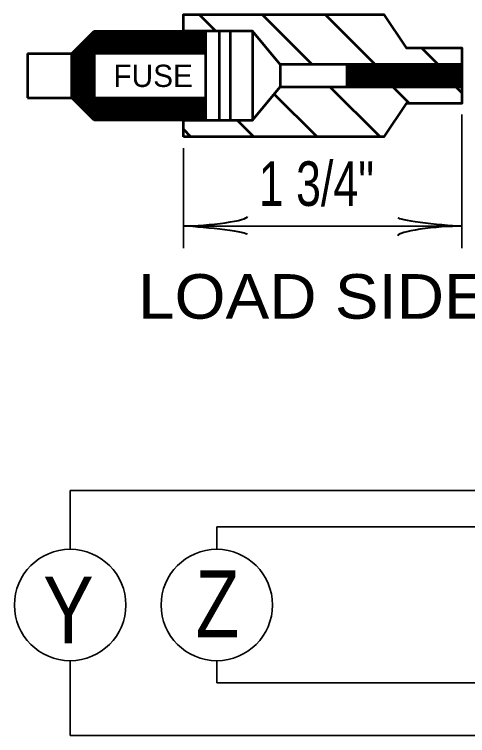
# Model space of a CAD drawing. Extents: x -1 to 679, y 0 to 440.
# Drawn here: x 328.32 to 348.66, y 299.14 to 331.51 of the extents above; entities that cross this region are included whole.
import ezdxf

# ---------------------------------------------------------------- set-up
doc = ezdxf.new("R2010")
doc.units = 0
doc.header["$LTSCALE"] = 0.8
doc.layers.add('1', color=7, linetype='Continuous', lineweight=53)

msp = doc.modelspace()

# ---------------------------------------------------------------- linework, layer by layer
at = {"layer": '1'}
for p, q in [((337.3586, 330.7649), (336.6086, 331.5149)), ((341.687, 329.2649), (339.437, 331.5149)), ((344.5154, 329.2649), (342.2654, 331.5149)), ((330.9045, 329.7649), (331.9045, 330.7649)), ((330.9045, 329.7389), (331.9305, 330.7649)), ((330.9045, 329.5975), (332.0719, 330.7649)), ((330.9045, 329.4561), (332.2133, 330.7649)), ((330.9045, 329.3147), (332.3547, 330.7649)), ((330.9045, 329.1732), (332.4962, 330.7649)), ((330.9045, 329.0318), (332.6376, 330.7649)), ((330.9045, 328.8904), (332.779, 330.7649)), ((332.4819, 329.7649), (331.6932, 330.5536)), ((332.6233, 329.7649), (331.7639, 330.6243)), ((332.7647, 329.7649), (331.8346, 330.695)), ((331.9045, 330.7649), (335.9045, 330.7649)), ((332.9062, 329.7649), (331.9062, 330.7649)), ((331.9204, 329.7649), (332.9204, 330.7649)), ((333.0476, 329.7649), (332.0476, 330.7649)), ((332.0618, 329.7649), (333.0618, 330.7649)), ((333.189, 329.7649), (332.189, 330.7649)), ((332.2032, 329.7649), (333.2032, 330.7649)), ((333.3304, 329.7649), (332.3304, 330.7649)), ((332.3447, 329.7649), (333.3447, 330.7649)), ((333.4718, 329.7649), (332.4718, 330.7649)), ((332.4861, 329.7649), (333.4861, 330.7649)), ((333.6132, 329.7649), (332.6132, 330.7649)), ((332.6275, 329.7649), (333.6275, 330.7649)), ((333.7547, 329.7649), (332.7547, 330.7649)), ((332.7689, 329.7649), (333.7689, 330.7649)), ((333.8961, 329.7649), (332.8961, 330.7649)), ((332.9104, 329.7649), (333.9104, 330.7649)), ((334.0375, 329.7649), (333.0375, 330.7649)), ((333.0518, 329.7649), (334.0518, 330.7649)), ((334.1789, 329.7649), (333.1789, 330.7649)), ((333.1932, 329.7649), (334.1932, 330.7649)), ((334.3204, 329.7649), (333.3204, 330.7649)), ((333.3347, 329.7649), (334.3347, 330.7649)), ((334.4618, 329.7649), (333.4618, 330.7649)), ((333.4761, 329.7649), (334.4761, 330.7649)), ((334.6033, 329.7649), (333.6033, 330.7649)), ((333.6175, 329.7649), (334.6175, 330.7649)), ((334.7447, 329.7649), (333.7447, 330.7649)), ((333.7589, 329.7649), (334.7589, 330.7649)), ((334.8861, 329.7649), (333.8861, 330.7649)), ((333.9003, 329.7649), (334.9003, 330.7649)), ((335.0275, 329.7649), (334.0275, 330.7649)), ((334.0417, 329.7649), (335.0417, 330.7649)), ((335.1689, 329.7649), (334.1689, 330.7649)), ((334.1832, 329.7649), (335.1832, 330.7649)), ((335.3103, 329.7649), (334.3103, 330.7649)), ((334.3246, 329.7649), (335.3246, 330.7649)), ((335.4518, 329.7649), (334.4518, 330.7649)), ((334.466, 329.7649), (335.466, 330.7649)), ((335.5932, 329.7649), (334.5932, 330.7649)), ((334.6074, 329.7649), (335.6074, 330.7649)), ((335.7346, 329.7649), (334.7346, 330.7649)), ((334.7488, 329.7649), (335.7488, 330.7649)), ((335.876, 329.7649), (334.876, 330.7649)), ((334.8902, 329.7649), (335.8902, 330.7649)), ((336.0174, 329.7649), (335.0174, 330.7649)), ((335.0317, 329.7649), (336.0317, 330.7649)), ((336.1588, 329.7649), (335.1588, 330.7649)), ((335.1731, 329.7649), (336.1731, 330.7649)), ((336.3003, 329.7649), (335.3003, 330.7649)), ((335.3145, 329.7649), (336.3145, 330.7649)), ((336.4417, 329.7649), (335.4417, 330.7649)), ((335.456, 329.7649), (336.456, 330.7649)), ((336.5831, 329.7649), (335.5831, 330.7649)), ((335.5974, 329.7649), (336.5974, 330.7649)), ((336.7245, 329.7649), (335.7245, 330.7649)), ((335.7388, 329.7649), (336.7388, 330.7649)), ((336.866, 329.7649), (335.866, 330.7649)), ((335.8802, 329.7649), (336.8802, 330.7649)), ((336.9045, 329.8678), (336.0074, 330.7649)), ((336.0217, 329.7649), (336.9045, 330.6477)), ((336.9045, 330.0093), (336.1488, 330.7649)), ((336.9045, 330.1507), (336.2903, 330.7649)), ((336.9045, 330.2921), (336.4317, 330.7649)), ((336.9045, 330.4335), (336.5731, 330.7649)), ((336.9045, 330.5749), (336.7145, 330.7649)), ((336.9045, 330.7163), (336.8559, 330.7649)), ((337.5045, 330.7649), (337.5045, 326.7649)), ((338.0045, 330.7649), (338.0045, 326.7649)), ((339.0045, 330.7649), (339.0045, 326.7649)), ((331.9162, 329.7649), (331.4103, 330.2707)), ((332.0577, 329.7649), (331.4811, 330.3415)), ((332.1991, 329.7649), (331.5517, 330.4122)), ((332.3405, 329.7649), (331.6225, 330.4829)), ((336.1631, 329.7649), (336.9045, 330.5063)), ((336.3045, 329.7649), (336.9045, 330.3649)), ((331.9045, 329.0695), (331.0568, 329.9172)), ((331.9045, 329.2109), (331.1275, 329.9879)), ((331.9045, 329.3523), (331.1982, 330.0587)), ((331.9045, 329.4937), (331.2689, 330.1293)), ((331.9045, 329.6352), (331.3397, 330.2001)), ((336.4459, 329.7649), (336.9045, 330.2235)), ((336.5873, 329.7649), (336.9045, 330.0821)), ((336.7287, 329.7649), (336.9045, 329.9407)), ((347.3438, 329.2649), (346.5938, 330.0149)), ((328.9045, 329.7649), (328.9045, 327.7649)), ((328.9045, 329.7649), (330.9045, 329.7649)), ((330.9045, 328.749), (331.9045, 329.749)), ((331.9045, 328.6452), (330.9045, 329.6452)), ((330.9045, 328.6076), (331.9045, 329.6076)), ((331.9045, 328.7867), (330.9154, 329.7758)), ((331.9045, 328.9281), (330.9861, 329.8465)), ((336.8702, 329.7649), (336.9045, 329.7992)), ((336.9045, 329.7649), (336.9045, 327.7649)), ((331.9045, 328.5038), (330.9045, 329.5038)), ((330.9045, 328.4662), (331.9045, 329.4662)), ((331.9045, 328.3624), (330.9045, 329.3624)), ((330.9045, 328.3247), (331.9045, 329.3247)), ((340.2545, 329.2649), (340.2545, 328.2649)), ((343.2545, 329.1599), (343.3595, 329.2649)), ((343.2545, 329.0185), (343.5009, 329.2649)), ((343.2545, 328.8771), (343.6423, 329.2649)), ((343.2545, 328.7357), (343.7837, 329.2649)), ((343.2545, 328.5942), (343.9252, 329.2649)), ((343.2545, 328.4528), (344.0666, 329.2649)), ((343.2545, 328.3114), (344.208, 329.2649)), ((344.2628, 328.2649), (343.2628, 329.2649)), ((343.3494, 328.2649), (344.3494, 329.2649)), ((344.4042, 328.2649), (343.4042, 329.2649)), ((343.4908, 328.2649), (344.4908, 329.2649)), ((344.5457, 328.2649), (343.5457, 329.2649)), ((343.6323, 328.2649), (344.6323, 329.2649)), ((344.6871, 328.2649), (343.6871, 329.2649)), ((343.7738, 328.2649), (344.7738, 329.2649)), ((344.8285, 328.2649), (343.8285, 329.2649)), ((343.9152, 328.2649), (344.9152, 329.2649)), ((344.9699, 328.2649), (343.9699, 329.2649)), ((344.0566, 328.2649), (345.0566, 329.2649)), ((345.1113, 328.2649), (344.1113, 329.2649)), ((344.198, 328.2649), (345.198, 329.2649)), ((345.2527, 328.2649), (344.2527, 329.2649)), ((344.3394, 328.2649), (345.3394, 329.2649)), ((345.3942, 328.2649), (344.3942, 329.2649)), ((344.4808, 328.2649), (345.4808, 329.2649)), ((345.5356, 328.2649), (344.5356, 329.2649)), ((344.6223, 328.2649), (345.6223, 329.2649)), ((345.677, 328.2649), (344.677, 329.2649)), ((344.7637, 328.2649), (345.7637, 329.2649)), ((345.8184, 328.2649), (344.8184, 329.2649)), ((344.9051, 328.2649), (345.9051, 329.2649)), ((345.9598, 328.2649), (344.9598, 329.2649)), ((345.0465, 328.2649), (346.0465, 329.2649)), ((346.1013, 328.2649), (345.1013, 329.2649)), ((345.1879, 328.2649), (346.1879, 329.2649)), ((346.2428, 328.2649), (345.2428, 329.2649)), ((345.3293, 328.2649), (346.3293, 329.2649)), ((346.3842, 328.2649), (345.3842, 329.2649)), ((345.4708, 328.2649), (346.4708, 329.2649)), ((346.5256, 328.2649), (345.5256, 329.2649)), ((345.6122, 328.2649), (346.6122, 329.2649)), ((346.667, 328.2649), (345.667, 329.2649)), ((345.7536, 328.2649), (346.7536, 329.2649)), ((346.8084, 328.2649), (345.8084, 329.2649)), ((345.895, 328.2649), (346.895, 329.2649)), ((346.9498, 328.2649), (345.9498, 329.2649)), ((346.0365, 328.2649), (347.0365, 329.2649)), ((347.0913, 328.2649), (346.0913, 329.2649)), ((346.1779, 328.2649), (347.1779, 329.2649)), ((347.2327, 328.2649), (346.2327, 329.2649)), ((346.3193, 328.2649), (347.3193, 329.2649)), ((347.3741, 328.2649), (346.3741, 329.2649)), ((346.4607, 328.2649), (347.4607, 329.2649)), ((347.5155, 328.2649), (346.5155, 329.2649)), ((346.6022, 328.2649), (347.6022, 329.2649)), ((347.6569, 328.2649), (346.6569, 329.2649)), ((346.7436, 328.2649), (347.7436, 329.2649)), ((347.7983, 328.2649), (346.7983, 329.2649)), ((346.885, 328.2649), (347.885, 329.2649)), ((347.9398, 328.2649), (346.9398, 329.2649)), ((347.0264, 328.2649), (348.0264, 329.2649)), ((348.0812, 328.2649), (347.0812, 329.2649)), ((347.1678, 328.2649), (348.1678, 329.2649)), ((348.2226, 328.2649), (347.2226, 329.2649)), ((347.3092, 328.2649), (348.3092, 329.2649)), ((348.364, 328.2649), (347.364, 329.2649)), ((348.4045, 328.3658), (347.5054, 329.2649)), ((348.4045, 328.5073), (347.6469, 329.2649)), ((348.4045, 328.6488), (347.7883, 329.2649)), ((348.4045, 328.7902), (347.9298, 329.2649)), ((348.4045, 328.9316), (348.0712, 329.2649)), ((348.4045, 329.073), (348.2126, 329.2649)), ((348.4045, 329.2144), (348.354, 329.2649)), ((331.9045, 328.221), (330.9045, 329.221)), ((330.9045, 328.1833), (331.9045, 329.1833)), ((331.9045, 328.0796), (330.9045, 329.0796)), ((330.9045, 328.0419), (331.9045, 329.0419)), ((331.9045, 327.9382), (330.9045, 328.9382)), ((344.1214, 328.2649), (343.2545, 329.1318)), ((343.98, 328.2649), (343.2545, 328.9904)), ((347.4507, 328.2649), (348.4045, 329.2188)), ((347.5921, 328.2649), (348.4045, 329.0773)), ((347.7335, 328.2649), (348.4045, 328.9359)), ((330.9045, 327.9005), (331.9045, 328.9005)), ((331.9045, 327.7967), (330.9045, 328.7967)), ((332.7949, 326.7649), (330.9045, 328.6553)), ((330.9074, 327.762), (331.9045, 328.759)), ((330.9782, 327.6912), (331.9045, 328.6176)), ((343.8386, 328.2649), (343.2545, 328.849)), ((343.6972, 328.2649), (343.2545, 328.7076)), ((347.8749, 328.2649), (348.4045, 328.7945)), ((348.0163, 328.2649), (348.4045, 328.6531)), ((332.6535, 326.7649), (330.9045, 328.5139)), ((332.5121, 326.7649), (330.9045, 328.3725)), ((331.0488, 327.6206), (331.9045, 328.4762)), ((331.1196, 327.5498), (331.9045, 328.3347)), ((343.5557, 328.2649), (343.2545, 328.5661)), ((343.4142, 328.2649), (343.2545, 328.4247)), ((343.2728, 328.2649), (343.2545, 328.2833)), ((348.1577, 328.2649), (348.4045, 328.5117)), ((348.2992, 328.2649), (348.4045, 328.3702)), ((332.3707, 326.7649), (330.9045, 328.2311)), ((332.2292, 326.7649), (330.9045, 328.0896)), ((331.1902, 327.4792), (331.9045, 328.1933)), ((331.261, 327.4084), (331.9045, 328.0519)), ((344.731, 326.0149), (342.481, 328.2649)), ((346.0594, 327.5149), (345.3094, 328.2649)), ((348.4045, 327.9982), (348.1378, 328.2649)), ((328.9045, 327.7649), (330.9045, 327.7649)), ((332.0877, 326.7649), (330.9045, 327.9482)), ((331.9463, 326.7649), (330.9045, 327.8067)), ((331.3317, 327.3377), (331.9045, 327.9105)), ((331.4024, 327.267), (331.9045, 327.7691)), ((331.4731, 327.1963), (332.0417, 327.7649)), ((331.5438, 327.1256), (332.1832, 327.7649)), ((331.6146, 327.0548), (332.3246, 327.7649)), ((331.6852, 326.9842), (332.466, 327.7649)), ((331.756, 326.9134), (332.6074, 327.7649)), ((331.8267, 326.8427), (332.7488, 327.7649)), ((331.8974, 326.772), (332.8902, 327.7649)), ((332.9363, 326.7649), (331.9363, 327.7649)), ((332.0317, 326.7649), (333.0317, 327.7649)), ((333.0777, 326.7649), (332.0777, 327.7649)), ((332.1731, 326.7649), (333.1731, 327.7649)), ((333.2192, 326.7649), (332.2192, 327.7649)), ((332.3145, 326.7649), (333.3145, 327.7649)), ((333.3606, 326.7649), (332.3606, 327.7649)), ((332.456, 326.7649), (333.456, 327.7649)), ((333.502, 326.7649), (332.502, 327.7649)), ((332.5974, 326.7649), (333.5974, 327.7649)), ((333.6434, 326.7649), (332.6434, 327.7649)), ((332.7388, 326.7649), (333.7388, 327.7649)), ((333.7848, 326.7649), (332.7848, 327.7649)), ((332.8802, 326.7649), (333.8802, 327.7649)), ((333.9262, 326.7649), (332.9262, 327.7649)), ((333.0217, 326.7649), (334.0217, 327.7649)), ((334.0677, 326.7649), (333.0677, 327.7649)), ((333.1631, 326.7649), (334.1631, 327.7649)), ((334.2091, 326.7649), (333.2091, 327.7649)), ((333.3045, 326.7649), (334.3045, 327.7649)), ((334.3505, 326.7649), (333.3505, 327.7649)), ((333.4459, 326.7649), (334.4459, 327.7649)), ((334.4919, 326.7649), (333.4919, 327.7649)), ((333.5873, 326.7649), (334.5873, 327.7649)), ((334.6333, 326.7649), (333.6333, 327.7649)), ((333.7287, 326.7649), (334.7287, 327.7649)), ((334.7748, 326.7649), (333.7748, 327.7649)), ((333.8702, 326.7649), (334.8702, 327.7649)), ((334.9162, 326.7649), (333.9162, 327.7649)), ((334.0116, 326.7649), (335.0116, 327.7649)), ((335.0577, 326.7649), (334.0577, 327.7649)), ((334.153, 326.7649), (335.153, 327.7649)), ((335.1991, 326.7649), (334.1991, 327.7649)), ((334.2944, 326.7649), (335.2944, 327.7649)), ((335.3405, 326.7649), (334.3405, 327.7649)), ((334.4358, 326.7649), (335.4358, 327.7649)), ((335.4819, 326.7649), (334.4819, 327.7649)), ((334.5772, 326.7649), (335.5772, 327.7649)), ((335.6233, 326.7649), (334.6233, 327.7649)), ((334.7187, 326.7649), (335.7187, 327.7649)), ((335.7647, 326.7649), (334.7647, 327.7649)), ((334.8602, 326.7649), (335.8602, 327.7649)), ((335.9062, 326.7649), (334.9062, 327.7649)), ((335.0016, 326.7649), (336.0016, 327.7649)), ((336.0476, 326.7649), (335.0476, 327.7649)), ((335.143, 326.7649), (336.143, 327.7649)), ((336.189, 326.7649), (335.189, 327.7649)), ((335.2844, 326.7649), (336.2844, 327.7649)), ((336.3304, 326.7649), (335.3304, 327.7649)), ((335.4258, 326.7649), (336.4258, 327.7649)), ((336.4718, 326.7649), (335.4718, 327.7649)), ((335.5673, 326.7649), (336.5673, 327.7649)), ((336.6132, 326.7649), (335.6132, 327.7649)), ((335.7087, 326.7649), (336.7087, 327.7649)), ((336.7547, 326.7649), (335.7547, 327.7649)), ((335.8501, 326.7649), (336.8501, 327.7649)), ((336.8961, 326.7649), (335.8961, 327.7649)), ((335.9915, 326.7649), (336.9045, 327.6779)), ((336.9045, 326.8979), (336.0375, 327.7649)), ((336.9045, 327.0393), (336.1789, 327.7649)), ((336.9045, 327.1808), (336.3204, 327.7649)), ((336.9045, 327.3222), (336.4618, 327.7649)), ((336.9045, 327.4637), (336.6033, 327.7649)), ((336.9045, 327.6051), (336.7447, 327.7649)), ((336.9045, 327.7465), (336.8861, 327.7649)), ((341.9026, 326.0149), (339.9809, 327.9366)), ((336.1329, 326.7649), (336.9045, 327.5365)), ((336.2743, 326.7649), (336.9045, 327.3951)), ((336.4158, 326.7649), (336.9045, 327.2537)), ((336.5572, 326.7649), (336.9045, 327.1123)), ((335.9045, 326.7649), (331.9045, 326.7649)), ((336.6986, 326.7649), (336.9045, 326.9708)), ((336.84, 326.7649), (336.9045, 326.8294)), ((339.0742, 326.0149), (338.3242, 326.7649)), ((336.2457, 326.0149), (335.9045, 326.3562))]:
    msp.add_line(p, q, dxfattribs=at)
at = {"layer": '1', "lineweight": 35}
for p, q in [((348.4045, 327.0149), (348.4045, 321.0149)), ((335.9045, 325.5149), (335.9045, 321.0149)), ((335.9045, 322.0149), (348.4045, 322.0149)), ((350.9045, 310.1399), (330.8241, 310.1399)), ((330.8241, 310.1399), (330.8241, 307.5011)), ((355.9045, 308.5149), (337.4045, 308.5149)), ((337.4045, 308.5149), (337.4045, 307.5011)), ((330.8241, 302.5011), (330.8241, 299.1399)), ((337.4045, 302.5011), (337.4045, 301.5149)), ((337.4045, 301.5149), (425.9044, 301.5149)), ((330.8241, 299.1399), (373.7847, 299.1399))]:
    msp.add_line(p, q, dxfattribs=at)
at = {"layer": '1'}
for points in [[(335.9045, 330.7649), (335.9045, 331.5149), (344.9045, 331.5149), (345.9045, 330.0149), (348.4045, 330.0149), (348.4045, 329.2649), (343.2545, 329.2649), (340.2545, 329.2649), (339.0045, 330.7649)], [(343.2545, 328.2649), (343.2545, 329.2649), (348.4045, 329.2649), (348.4045, 328.2649)], [(335.9045, 326.0149), (335.9045, 326.7649), (339.0045, 326.7649), (340.2545, 328.2649), (343.2545, 328.2649), (348.4045, 328.2649), (348.4045, 327.5149), (345.9045, 327.5149), (344.9045, 326.0149)]]:
    msp.add_lwpolyline(points, close=True, dxfattribs=at)
for points in [[(336.9045, 330.7649), (336.9045, 329.7649), (331.9045, 329.7649), (331.9045, 327.7649), (336.9045, 327.7649), (336.9045, 326.7649)], [(331.9045, 326.7649), (330.9045, 327.7649), (330.9045, 329.7649)]]:
    msp.add_lwpolyline(points, dxfattribs=at)
at = {"layer": '1', "lineweight": 35}
for centre in [(330.8241, 305.0011), (337.4045, 305.0011)]:
    msp.add_circle(centre, 2.5, dxfattribs=at)
at = {"layer": '1', "lineweight": 40}
for centre, major_axis, ratio, start_param, end_param in [((336.9957, 322.2912), (-1.7857, -0.1562), 0.122415, 0.8963533, 3.1415927), ((347.284, 322.2265), (1.7565, -0.1757), 0.07063, 3.1407148, 5.41811), ((337.025, 321.8033), (-1.7565, 0.1757), 0.07063, 3.1407148, 5.41811), ((347.3133, 321.7386), (1.7857, 0.1562), 0.122415, 0.8963533, 3.1415927)]:
    msp.add_ellipse(centre, major_axis=major_axis, ratio=ratio, start_param=start_param, end_param=end_param, dxfattribs=at)

# ---------------------------------------------------------------- texts
at = {"layer": '1'}
msp.add_text('FUSE', height=1, dxfattribs=at).set_placement((332.7668, 328.2581))
for s, height, width, p in [('1 3/4"', 2, 0.75, (339.2905, 322.9182)), ('LOAD SIDE', 2, 1.1, (333.8728, 317.8553)), ('Y', 3, 0.85, (329.6077, 303.2798)), ('Z', 3, 0.8, (336.4544, 303.5537))]:
    msp.add_text(s, height=height, dxfattribs=dict(at, width=width)).set_placement(p)

doc.saveas('drawing.dxf')
